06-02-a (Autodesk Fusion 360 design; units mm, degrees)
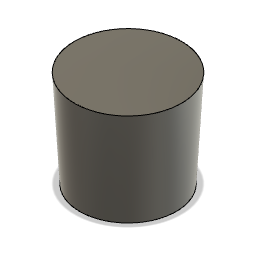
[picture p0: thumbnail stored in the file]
sketch "スケッチ" plane through (0, 0, 0) normal (0, 0, 1) x axis (1, 0, 0)
  line L1 (0, 45) -> (0, 0)
  line L2 (-25, 45) -> (0, 45)
  line L3 (-22.5, 0) -> (-25, 45)
  line L4 (0, 0) -> (-22.5, 0)
  point P1 (0, 0)
  point P2 (0, 0)
  point P3 (0, 45)
  point P5 (-22.5, 0)
  coincident P1 P2
  vertical L1
  perpendicular L1 L2
  perpendicular L1 L4
  dimension "d1" = 50
  dimension "d2" distance P2 P3 = 45
  dimension "d3" distance L1 P5 = 45
revolve "回転" sketch "スケッチ" AlongAngle 360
